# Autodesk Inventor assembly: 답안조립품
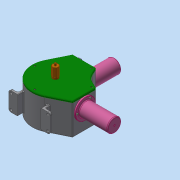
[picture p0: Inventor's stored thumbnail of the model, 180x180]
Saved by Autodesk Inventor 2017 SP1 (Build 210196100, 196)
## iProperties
Part Number: 답안조립품
Material: 일반
Document SubType Name: Assembly
Designer: MRC
Mass: 3748.68 g
Surface Area: 4101.78 cm^2
Volume: 1119.43 cm^3
Density: 3.34872 g/cm^3
Author: MRC
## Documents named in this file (13)
- C:\Users\MRC\Desktop\611109V1010\답안조립품.iam
- C:\Users\MRC\Desktop\611109V1010\본체.ipt
- C:\Users\MRC\Desktop\611109V1010\너트 M3.ipt
- C:\Users\MRC\Desktop\611109V1010\베어링 20 x 37 x 9.ipt
- C:\Users\MRC\Desktop\611109V1010\볼트 M3 x 12.ipt
- C:\Users\MRC\Desktop\611109V1010\실린더.ipt
- C:\Users\MRC\Desktop\611109V1010\앞커버.ipt
- C:\Users\MRC\Desktop\611109V1010\축.ipt
- C:\Users\MRC\Desktop\611109V1010\측정게이지.ipt
- C:\Users\MRC\Desktop\611109V1010\커넥팅로드 캡.ipt
- C:\Users\MRC\Desktop\611109V1010\커넥팅로드.ipt
- C:\Users\MRC\Desktop\611109V1010\피스톤 핀.ipt
- C:\Users\MRC\Desktop\611109V1010\피스톤.ipt
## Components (4 placed, 2 different names)
1. 피스톤 핀:1
2. 피스톤:1
3. 피스톤:2
4. 피스톤 핀:2
